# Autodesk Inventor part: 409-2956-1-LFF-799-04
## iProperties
Created: 2010-11
Part Number: 409-2956-1-LFF-799-04
Material: 3/4" OD TUBE - SS
Document SubType Name: Modeling
Designer: S. Boerckel
Engineer: Steve Boerckel
Mass: 731.966 g
Surface Area: 1099.2 cm^2
Volume: 90.5898 cm^3
Density: 8.08 g/cm^3
Description: DRAIN TUBING
Length: 38.702 in
Author: S. Boerckel
Revision Number: 0
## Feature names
1. Sweep2
